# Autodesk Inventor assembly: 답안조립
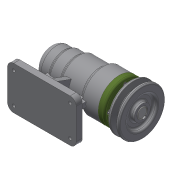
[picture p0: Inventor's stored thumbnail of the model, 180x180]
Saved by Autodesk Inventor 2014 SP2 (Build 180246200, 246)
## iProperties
Created: 2016-06
Part Number: 답안조립
Document SubType Name: Assembly
Designer: 201-20
Author: 201-20
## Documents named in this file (12)
- C:\Users\201-20\Desktop\460607V1028\답안조립.iam
- C:\Users\201-20\Desktop\460607V1028\부품1.ipt
- C:\Users\201-20\Desktop\460607V1028\축.ipt
- C:\Users\201-20\Desktop\460607V1028\베어링 6004.ipt
- C:\Users\201-20\Desktop\460607V1028\베어링 51202.ipt
- C:\Users\201-20\Desktop\460607V1028\어댑터슬리브.ipt
- C:\Users\201-20\Desktop\460607V1028\볼트 M4 x 12.ipt
- C:\Users\201-20\Desktop\460607V1028\커버.ipt
- C:\Users\201-20\Desktop\460607V1028\키 5 x 5 x 16.ipt
- C:\Users\201-20\Desktop\460607V1028\V벨트풀리.ipt
- C:\Users\201-20\Desktop\460607V1028\오일 실.ipt
- C:\Users\201-20\Desktop\460607V1028\멈춤나사 M3x8.ipt
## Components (6 placed, 2 different names)
1. ISO 4762 M4 x 12:1
2. V벨트풀리:1 — 플러쉬:1
3. ISO 4762 M4 x 12:2
4. ISO 4762 M4 x 12:3
5. ISO 4762 M4 x 12:4
6. ISO 4762 M4 x 12:5
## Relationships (1: Flush 1)
- 플러쉬:1 [Flush]: V벨트풀리:1
